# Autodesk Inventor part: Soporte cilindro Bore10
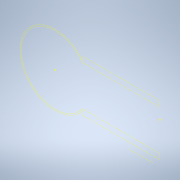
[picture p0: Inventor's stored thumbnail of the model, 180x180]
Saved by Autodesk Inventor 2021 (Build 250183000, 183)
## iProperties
Created: 2021-03
Part Number: Soporte cilindro Bore10
Material: Genérico
Document SubType Name: Modeling
Designer: ATOUZA
Density: 1 g/cm^3
Appearance: Valor por defecto
Author: ATOUZA
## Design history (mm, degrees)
sketch "Boceto1"
  geometry: L1 (-8, -4.75)-(-0.1, -4.75) reference; L2 (-8, -4.75)-(-12.563, -4.75) reference; L3 (-12.563, -4.75)-(-12.563, -5.65) reference; L4 (-12.563, -5.65)-(-0.1, -5.65) reference; L5 (-0.1, -5.65)-(-0.1, -4.75) reference; L6 (-0.1, 2.65)-(-12.563, 2.65) reference; L7 (-12.563, 2.65)-(-12.563, 1.75) reference; L8 (-12.563, 1.75)-(-8, 1.75) reference; L9 (-0.1, 1.75)-(-8, 1.75) reference; L10 (-0.1, 1.75)-(-0.1, 2.65) reference; L11 (-5.1, -6.65)-(-1.1, -6.65) reference; L12 (-9.15, -0.15)-(-8.65, -0.15) reference; L13 (-8.65, -2.85)-(-9.15, -2.85) reference; L14 (-7.472, -2.9)-(-6.3, -2.9) reference; L15 (-6.3, -2.9)-(-6.3, -0.1) reference; L16 (-6.3, -0.1)-(-7.472, -0.1) reference; L17 (-9.15, -0.15)-(-8.65, -0.15) reference; L18 (-7.577, 0)-(-6, 0) reference; L19 (-6, 0)-(-6, 1.275); L20 (-6, 1.275)-(-8.11, 1.275) reference; L21 (-8.91, 1.675)-(-11.2, 1.675) reference; L22 (-11.2, 1.675)-(-11.2, -4.675) reference; L23 (-6.3, -2.9)-(-6.3, -0.1) reference; L24 (-6.3, -0.1)-(-7.472, -0.1) reference; L25 (-7.404, 0)-(-6, 0); L26 (-6, -0.1)-(-7.31, -0.1); L27 (-5.1, -1.5)-(-12.389, -1.5); L28 (-11.2, 1.675)-(-11.2, 0.013); L29 (-11.2, 0.013)-(-10.383, 0.013); L30 (-6, -0.1)-(-6, 1.75); L31 (-11.2, 1.675)-(-12.509, 1.675); L32 (-12.482, 2.65)-(-0.1, 2.65); L33 (-0.1, 1.75)-(-6, 1.75); L34 (-0.1, 2.65)-(-0.1, 1.75); L35 (-0.1, -4.75)-(-6, -4.75); L36 (-0.1, -5.65)-(-0.1, -4.75); L37 (-12.482, -5.65)-(-0.1, -5.65); L38 (-6, -2.9)-(-6, -4.75); L39 (-6, -2.9)-(-7.31, -2.9); L40 (-11.2, -4.675)-(-11.2, -3.013); L41 (-11.2, -4.675)-(-12.509, -4.675); L42 (-10.383, -3.013)-(-11.2, -3.013); L43 (-16.987, 7.098)-(-16.987, -10.799); L44 (-21.41, -5.65)-(-33.873, -5.65); L45 (-21.491, -5.65)-(-27.491, -5.65); L46 (-33.873, 2.65)-(-21.41, 2.65); L47 (-21.491, 2.65)-(-27.491, 2.65); L48 (-33.873, 1.75)-(-33.873, 2.65); L49 (-33.873, -5.65)-(-33.873, -4.75); L50 (-26.396, 0)-(-27.973, 0); L51 (-26.57, 0)-(-27.973, 0); L52 (-33.873, -5.65)-(-33.873, -4.75); L53 (-27.491, 2.65)-(-27.491, -5.65); L54 (-17, -1.5)-(-33.873, -1.5); L55 (-17, -1.6)-(-33.873, -1.6); L56 (-17, -1.4)-(-33.873, -1.4); L57 (-22.499, -1.4)-(-27.491, -1.4); L58 (-22.499, -1.6)-(-27.491, -1.6); L59 (-27.491, 2.65)-(-27.491, -1.4); L60 (-27.491, -1.6)-(-27.491, -5.65); A1 r 5.5 centre (-17, -1.5) between (-12.563, 1.75) and (-12.563, -4.75) reference; A2 r 5.7 centre (-17, -1.5) between (-12.563, 2.078) and (-12.563, -5.078) reference; A3 r 1.35 centre (-8.65, -1.5) between (-8.65, -2.85) and (-8.65, -0.15) reference; A4 r 1.35 centre (-9.15, -1.5) between (-9.15, -0.15) and (-9.15, -2.85) reference; A5 r 2 centre (-8.9, -1.5) between (-7.472, -0.1) and (-7.472, -2.9) reference; A6 r 1.35 centre (-8.65, -1.5) between (-8.65, -2.85) and (-8.65, -0.15) reference; A7 r 1.35 centre (-9.15, -1.5) between (-9.15, -0.15) and (-9.15, -2.85) reference; A8 r 1 centre (-8.11, 2.275) between (-8.91, 1.675) and (-8.11, 1.275) reference; A9 r 2 centre (-8.9, -1.5) between (-7.472, -0.1) and (-7.577, 0) reference; A10 r 2.119 centre (-8.9, -1.5) between (-7.31, -0.1) and (-10.383, 0.013); A11 r 2.119 centre (-8.9, -1.5) between (-10.383, -3.013) and (-7.31, -2.9); A12 r 5.5 centre (-17, -1.5) between (-12.509, 1.675) and (-22.499, -1.4); A13 r 5.5 centre (-17, -1.5) between (-22.499, -1.6) and (-12.509, -4.675); A14 r 6.135 centre (-17, -1.5) between (-12.482, 2.65) and (-21.518, 2.65); A15 r 6.135 centre (-17, -1.5) between (-21.518, -5.65) and (-12.482, -5.65); 8 further points
  constraints: 74 end point, 21 symmetric about line, 14 point on line, 13 point on circle, 6 centre point, 4 horizontal, 4 perpendicular, 3 coincident, 3 parallel, 3 vertical, 2 collinear, 1 other
  dimensions: "d1" = 0.1 distance between parallel lines of L54 L55; "d2" = 0.1 distance between parallel lines of L54 L56; "d3" = 12.38226 distance of L37.start L4.end; "d4" = 6 distance of L45.start L45.end
extrude "Extrusión1" new body sketch "Boceto1" distance "d5" = 8; taper "d6" = 0 deg
node "Sólido1"
node "Referencia1"
node "Referencia2"
node "Referencia3"
node "Referencia4"
node "Referencia5"
node "Referencia6"
other parameters: "d0" = 4.2
